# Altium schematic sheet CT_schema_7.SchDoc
size 278 x 170 mm
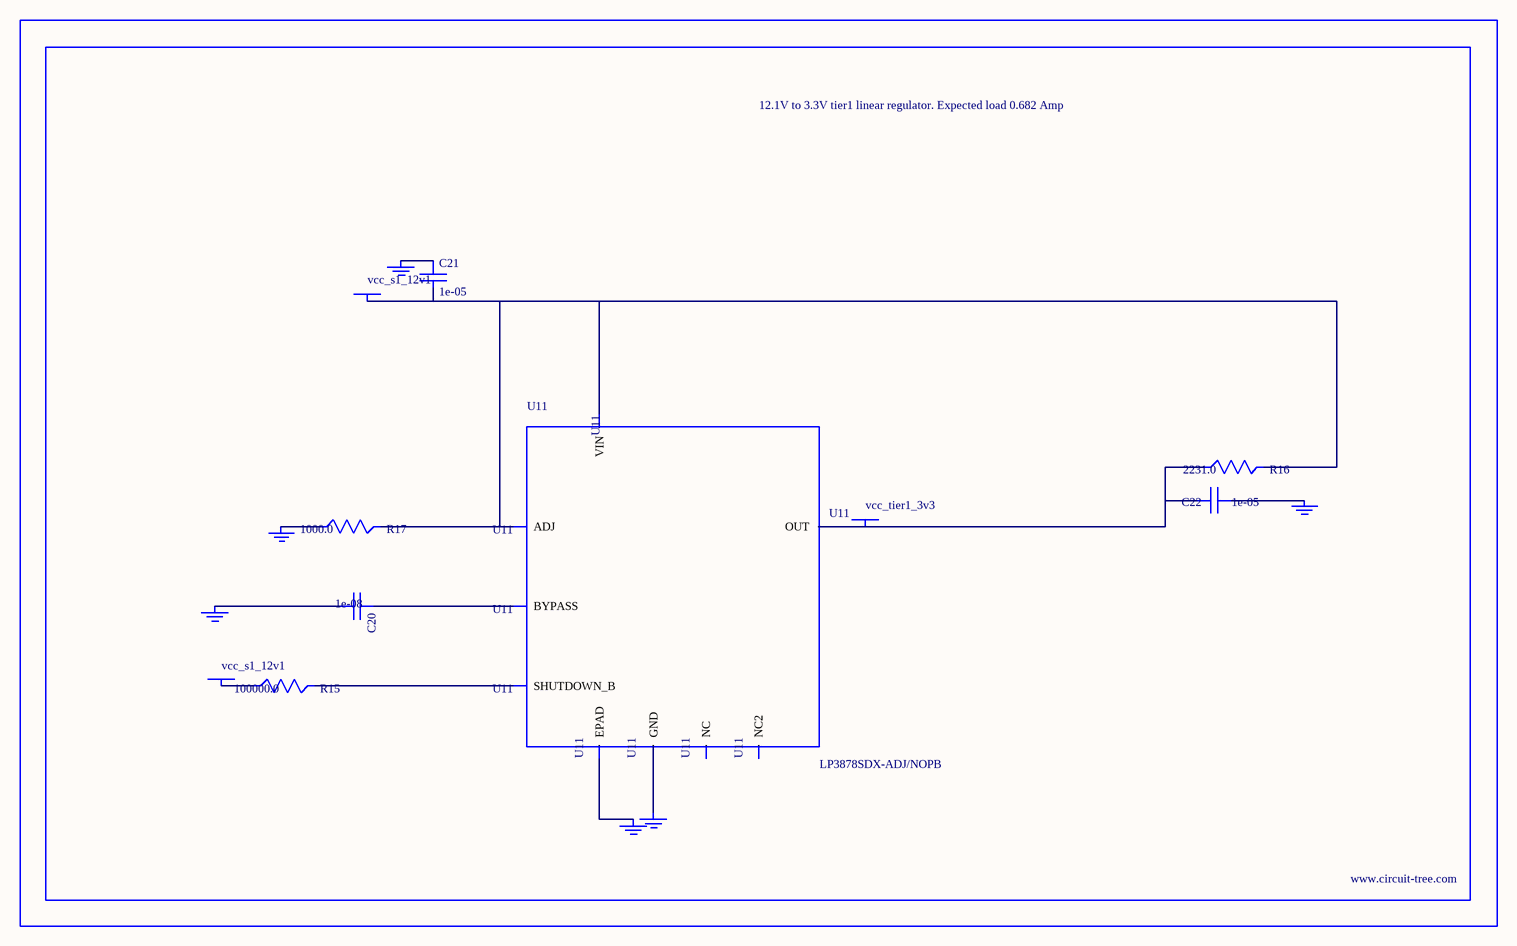
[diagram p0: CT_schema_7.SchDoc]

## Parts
BORDER6  (no value)
C20  1e-08  [C0402]
C21  1e-05  [C1210]
C22  1e-05  [C1210]
GND_INSTANCE_6_0  (no value)
GND_INSTANCE_6_1  (no value)
GND_INSTANCE_6_2  (no value)
GND_INSTANCE_6_3  (no value)
GND_INSTANCE_6_4  (no value)
GND_INSTANCE_6_5  (no value)
POWER_INSTANCE_6_0  vcc_s1_12v1
POWER_INSTANCE_6_1  vcc_s1_12v1
POWER_INSTANCE_6_2  vcc_tier1_3v3
R15  100000.0  [R0603]
R16  2231.0  [R0603]
R17  1000.0  [R0603]
U11  LP3878SDX-ADJ/NOPB  [WSON-8]

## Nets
NetC20_1: C20.1 U11.1(BYPASS)
NetC20_2: C20.2 GND_INSTANCE_6_0.0(GND)
NetC21_1: C21.1 GND_INSTANCE_6_1.0(GND)
NetC21_2: C21.2 POWER_INSTANCE_6_0.0(PWR) R16.2 R17.2 U11.4(VIN) U11.6(ADJ)
NetC22_1: C22.1 GND_INSTANCE_6_2.0(GND)
NetC22_2: C22.2 POWER_INSTANCE_6_2.0(PWR) R16.1 U11.5(OUT)
NetGND_INSTANCE_6_3_0: GND_INSTANCE_6_3.0(GND) R17.1
NetGND_INSTANCE_6_4_0: GND_INSTANCE_6_4.0(GND) U11.PAD(EPAD)
NetGND_INSTANCE_6_5_0: GND_INSTANCE_6_5.0(GND) U11.3(GND)
NetPOWER_INSTANCE_6_1_0: POWER_INSTANCE_6_1.0(PWR) R15.1
NetR15_2: R15.2 U11.8(SHUTDOWN_B)

Not connected (* = marked no-connect by the designer): U11 2(NC) 7(NC2)

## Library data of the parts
BORDER6 = BORDER_PAGE6
C20 = C0402C103K3RAC
C21 = C1210C106K5PACTU
C22 = GRM32DR61E106MA12L
GND_INSTANCE_6_0-GND_INSTANCE_6_5 = GND
POWER_INSTANCE_6_0-POWER_INSTANCE_6_2 = PWR
R15 = RC0603JR-07100KL
R16 = R16
R17 = RC0603JR-071KL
